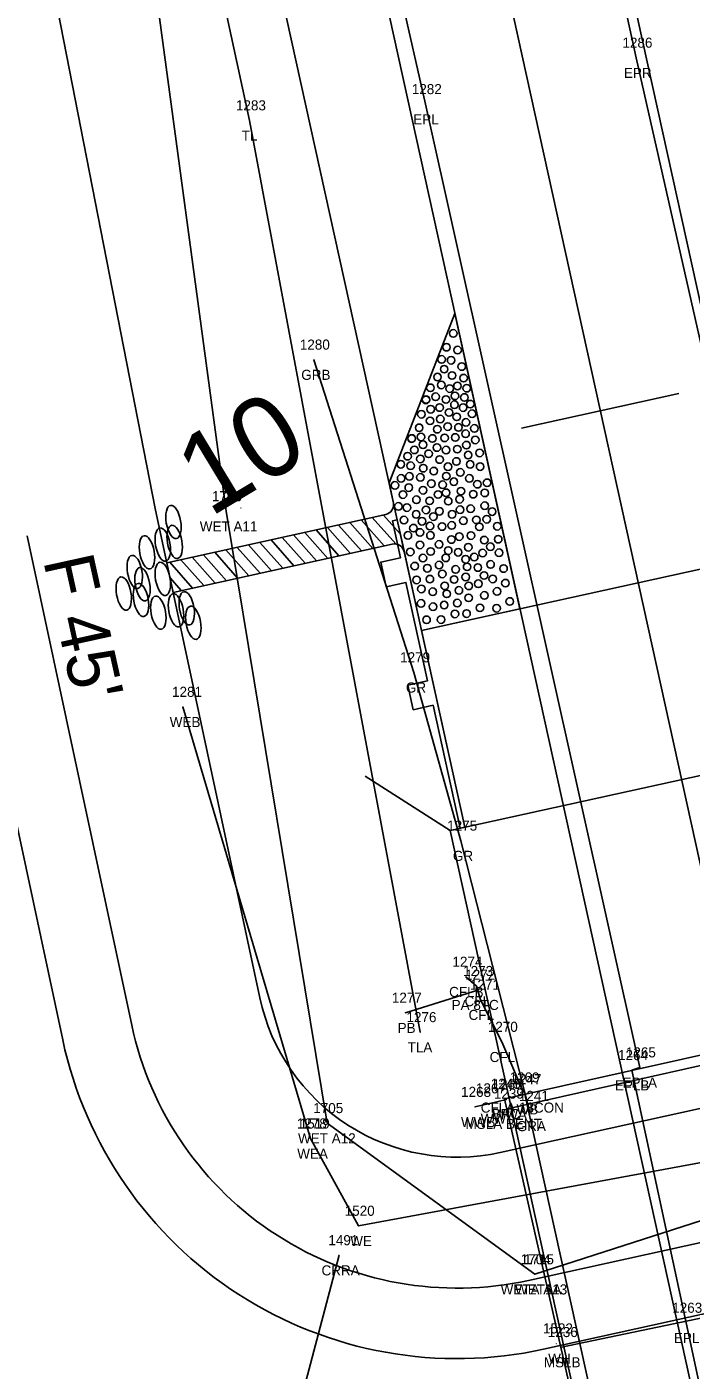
# Model space of a CAD drawing. Extents: x 2521558 to 2524785, y 882711 to 887632.
# Drawn here: x 2523710.8 to 2523776.7, y 885124.5 to 885257.9 of the extents above; entities that cross this region are included whole.
import ezdxf

# ---------------------------------------------------------------- set-up
doc = ezdxf.new("R2010")
doc.units = 0
for name, color, linetype in [('RD_EV_JW', 7, 'Continuous'), ('RD_EX_BldgApp', 7, 'Continuous'), ('RD_EX_BldgApp_txCode', 7, 'Continuous'), ('RD_EX_Bridge', 7, 'Continuous'), ('RD_EX_Bridge_txCode', 7, 'Continuous'), ('RD_EX_Conc', 7, 'Continuous'), ('RD_EX_Conc_txCode', 7, 'Continuous'), ('RD_EX_DR_Pipe', 7, 'Continuous'), ('RD_EX_DR_Pipe_txCode', 7, 'Continuous'), ('RD_EX_GuardRail', 7, 'Continuous'), ('RD_EX_GuardRail_txCode', 7, 'Continuous'), ('RD_EX_H2O', 7, 'Continuous'), ('RD_EX_H2O_txCode', 7, 'Continuous'), ('RD_EX_H2O_WetLd_txCode', 7, 'Continuous'), ('RD_EX_Misc', 7, 'Continuous'), ('RD_EX_Misc_txCode', 7, 'Continuous'), ('RD_EX_Road', 7, 'Continuous'), ('RD_EX_Road_txCode', 7, 'Continuous'), ('RD_EX_VEG', 7, 'Continuous'), ('RD_EX_VEG_txCode', 7, 'Continuous'), ('RD_HC_Cl', 7, 'Continuous'), ('RD_HC_Data_Tic', 7, 'Continuous'), ('RD_HC_TX_Sta50', 7, 'Continuous'), ('RD_PD_BCA', 7, 'Continuous'), ('RD_PD_Bridge', 7, 'Continuous'), ('RD_PD_CstnLmt', 7, 'Continuous'), ('RD_PD_DR_ErosCtrl', 7, 'Continuous'), ('RD_PD_Final_TrvlWay', 7, 'Continuous'), ('RD_PD_GR', 7, 'Continuous'), ('RD_PD_PaveShd', 7, 'Continuous'), ('RD_SMD_Locator', 7, 'Continuous')]:
    doc.layers.add(name, color=color, linetype=linetype)

# ---------------------------------------------------------------- blocks, each defined once
blk = doc.blocks.new('TBC1')
at = {"layer": 'RD_PD_GR'}
blk.add_lwpolyline([(12.5, 2.5), (15, 2.5), (15, 0.49), (25, 0.49), (25, 2.5), (27.5, 2.5), (27.5, 0.49), (31.25, 0.49), (31.25, 0), (0, 0), (0, 0.49), (12.5, 0.49)], close=True, dxfattribs=at)

msp = doc.modelspace()

# ---------------------------------------------------------------- linework, layer by layer
at = {"layer": 'RD_EV_JW'}
for points in [[(2523761.17, 885134.03), (2523740.58, 885149.03), (2523730.55, 885209.77), (2523710.6, 885357.47), (2523698.09, 885411.19), (2523674.93, 885498.62), (2523657.6, 885564.24), (2523640.82, 885610.87), (2523583.66, 885726.91), (2523539.21, 885693.17), (2523494.42, 885646.98)], [(2523761.17, 885134.03), (2523808.21, 885149.21), (2523821.91, 885178.64), (2523802.85, 885236.55), (2523777.81, 885305.56), (2523748.2, 885444.32), (2523730.68, 885516.88), (2523708.64, 885617.3), (2523698.71, 885662.02), (2523727.83, 885665.82), (2523757.3, 885671.75)]]:
    msp.add_lwpolyline(points, dxfattribs=at)
at = {"layer": 'RD_EX_BldgApp'}
msp.add_lwpolyline([(2523776.68, 885077.92), (2523768.27, 885115.31), (2523760.2, 885151.9)], dxfattribs=at)
at = {"layer": 'RD_EX_Bridge'}
for points in [[(2523774.91, 885077.6), (2523821.2, 885087.83), (2523805.06, 885161.89), (2523758.15, 885151.44), (2523774.91, 885077.6)], [(2523758.38, 885151.39), (2523756.7, 885150.99), (2523755.23, 885150.64)]]:
    msp.add_lwpolyline(points, dxfattribs=at)
at = {"layer": 'RD_EX_Conc'}
msp.add_lwpolyline([(2523760.04, 885152.08), (2523757.9, 885157.1), (2523755.8, 885161.28), (2523755.4, 885162.64), (2523754.34, 885163.56)], dxfattribs=at)
at = {"layer": 'RD_EX_DR_Pipe'}
msp.add_line((2523755.61, 885162.27), (2523748.33, 885159.99), dxfattribs=at)
at = {"layer": 'RD_EX_GuardRail'}
for p, q in [((2523749.16, 885193.78), (2523739.25, 885224.82)), ((2523753.83, 885177.07), (2523749.16, 885193.78)), ((2523760.65, 885150.24), (2523753.83, 885177.07))]:
    msp.add_line(p, q, dxfattribs=at)
at = {"layer": 'RD_EX_H2O'}
msp.add_line((2523738.91, 885147.5), (2523726.24, 885190.35), dxfattribs=at)
for points in [[(2523738.91, 885147.5), (2523743.69, 885138.84), (2523816.36, 885152.29), (2523822.43, 885163.3), (2523826.93, 885206.61)], [(2523741.75, 885135.92), (2523732.18, 885099.57), (2523664.9, 885060.26), (2523614.86, 885022.02), (2523558.95, 884972.63), (2523560.62, 884942.42), (2523490.01, 884911.76)]]:
    msp.add_lwpolyline(points, dxfattribs=at)
at = {"layer": 'RD_EX_Misc'}
for p, q in [((2523758.45, 885150.47), (2523805.66, 885161.06)), ((2523810.71, 885136.57), (2523763.83, 885126.8))]:
    msp.add_line(p, q, dxfattribs=at)
at = {"layer": 'RD_EX_Road'}
for p, q in [((2523771.24, 885254.79), (2523751.35, 885344.92)), ((2523750.32, 885250.18), (2523730.02, 885340.63)), ((2523792.78, 885159.31), (2523771.24, 885254.79)), ((2523771.58, 885154.56), (2523750.32, 885250.18)), ((2523770.8, 885154.29), (2523771.58, 885154.56)), ((2523776.18, 885129.21), (2523770.8, 885154.29)), ((2523781.52, 885104.77), (2523776.18, 885129.21))]:
    msp.add_line(p, q, dxfattribs=at)
at = {"layer": 'RD_EX_VEG'}
msp.add_lwpolyline([(2523749.81, 885158.06), (2523732.86, 885248.57), (2523691.62, 885438.95), (2523639.52, 885601.04)], dxfattribs=at)
at = {"layer": 'RD_HC_Cl'}
msp.add_line((2523641.17, 885794.2), (2524197.76, 883266.56), dxfattribs=at)
at = {"layer": 'RD_HC_Data_Tic'}
for q in [(2523775.47, 885221.48), (2523759.85, 885218.04)]:
    msp.add_line((2523767.66, 885219.76), q, dxfattribs=at)
at = {"layer": 'RD_PD_BCA'}
msp.add_line((2523703.95, 885205.86), (2523714.34, 885157.3), dxfattribs=at)
msp.add_lwpolyline([(2523762.05, 885126.6), (2523810.84, 885137.34)], dxfattribs=at)
msp.add_arc((2523753.45, 885165.66), 40, 192.0677, 282.4185, dxfattribs=at)
at = {"layer": 'RD_PD_Bridge'}
for p, q in [((2523749.94, 885197.94), (2523792.91, 885207.4)), ((2523754.24, 885178.41), (2523749.94, 885197.94)), ((2523752.77, 885178.09), (2523744.35, 885183.47))]:
    msp.add_line(p, q, dxfattribs=at)
for points in [[(2523798.67, 885188.19), (2523752.77, 885178.09)], [(2523752.77, 885178.09), (2523780.73, 885051.13)]]:
    msp.add_lwpolyline(points, dxfattribs=at)
at = {"layer": 'RD_PD_CstnLmt'}
for p, q in [((2523704.35, 885308.21), (2523723.51, 885210.04)), ((2523723.51, 885210.04), (2523733.89, 885161.48))]:
    msp.add_line(p, q, dxfattribs=at)
msp.add_lwpolyline([(2523757.75, 885146.13), (2523806.54, 885156.87)], dxfattribs=at)
msp.add_arc((2523753.45, 885165.66), 20, 192.0677, 282.4185, dxfattribs=at)
at = {"layer": 'RD_PD_DR_ErosCtrl'}
msp.add_line((2523710.8, 885207.32), (2523721.18, 885158.76), dxfattribs=at)
msp.add_lwpolyline([(2523760.55, 885133.43), (2523809.33, 885144.17)], dxfattribs=at)
msp.add_arc((2523753.45, 885165.66), 33, 192.0677, 282.4185, dxfattribs=at)
at = {"layer": 'RD_PD_Final_TrvlWay'}
for p, q in [((2523741.74, 885393.25), (2524015.93, 884148.08)), ((2523718.31, 885388.09), (2523992.49, 884142.92))]:
    msp.add_line(p, q, dxfattribs=at)
at = {"layer": 'RD_PD_GR'}
msp.add_line((2523747.52, 885208.93), (2523699.13, 885428.66), dxfattribs=at)
at = {"layer": 'RD_PD_PaveShd'}
for p, q in [((2523753.25, 885229.39), (2523746.71, 885212.59)), ((2523759.7, 885200.09), (2523753.25, 885229.39)), ((2523747.36, 885209.66), (2523746.71, 885212.59)), ((2523746.38, 885209.44), (2523724.66, 885204.65)), ((2523745.09, 885206.09), (2523742.82, 885208.66)), ((2523746.21, 885206.34), (2523743.94, 885208.91)), ((2523747.37, 885206.53), (2523745.05, 885209.15)), ((2523747.82, 885207.53), (2523746.17, 885209.4)), ((2523748, 885206.73), (2523747.36, 885209.66)), ((2523739.51, 885204.86), (2523737.23, 885207.43)), ((2523740.63, 885205.1), (2523738.35, 885207.67)), ((2523741.74, 885205.35), (2523739.47, 885207.92)), ((2523742.86, 885205.6), (2523740.59, 885208.17)), ((2523743.98, 885205.84), (2523741.7, 885208.41)), ((2523725.29, 885201.72), (2523747.02, 885206.51)), ((2523732.81, 885203.38), (2523730.53, 885205.95)), ((2523733.92, 885203.62), (2523731.65, 885206.19)), ((2523735.04, 885203.87), (2523732.77, 885206.44)), ((2523736.16, 885204.12), (2523733.88, 885206.69)), ((2523737.27, 885204.36), (2523735, 885206.93)), ((2523738.39, 885204.61), (2523736.12, 885207.18)), ((2523748, 885206.73), (2523749.94, 885197.94)), ((2523749.94, 885197.94), (2523748, 885206.73)), ((2523724.66, 885204.65), (2523725.29, 885201.72)), ((2523727.22, 885202.14), (2523724.95, 885204.71)), ((2523728.34, 885202.39), (2523726.06, 885204.96)), ((2523729.46, 885202.64), (2523727.18, 885205.21)), ((2523730.57, 885202.88), (2523728.3, 885205.45)), ((2523731.69, 885203.13), (2523729.42, 885205.7)), ((2523726.1, 885201.9), (2523724.98, 885203.17)), ((2523759.7, 885200.09), (2523749.94, 885197.94))]:
    msp.add_line(p, q, dxfattribs=at)
for centre in [(2523753.08, 885227.43), (2523753.08, 885227.43), (2523752.41, 885226.06), (2523752.41, 885226.06), (2523753.51, 885225.78), (2523753.51, 885225.78), (2523751.93, 885224.85), (2523751.93, 885224.85), (2523752.87, 885224.76), (2523752.87, 885224.76), (2523751.52, 885223.1), (2523752.18, 885223.88), (2523752.18, 885223.88), (2523752.97, 885223.25), (2523752.97, 885223.25), (2523753.92, 885224.14), (2523753.92, 885224.14), (2523754.11, 885222.99), (2523754.11, 885222.99), (2523750.81, 885222.03), (2523750.81, 885222.03), (2523751.89, 885222.31), (2523751.89, 885222.31), (2523752.73, 885221.95), (2523752.73, 885221.95), (2523753.5, 885222.22), (2523753.5, 885222.22), (2523754.42, 885221.99), (2523754.42, 885221.99), (2523750.37, 885220.83), (2523750.38, 885220.87), (2523751.33, 885221.14), (2523751.33, 885221.14), (2523752.36, 885220.87), (2523752.36, 885220.87), (2523753.2, 885220.35), (2523753.2, 885220.35), (2523753.25, 885221.23), (2523753.25, 885221.23), (2523754.19, 885221.07), (2523754.19, 885221.07), (2523754.77, 885220.41), (2523754.77, 885220.41), (2523749.92, 885219.4), (2523749.92, 885219.4), (2523750.84, 885219.9), (2523750.84, 885219.9), (2523751.73, 885220.07), (2523751.73, 885220.07), (2523751.79, 885218.93), (2523751.79, 885218.93), (2523752.67, 885219.58), (2523752.67, 885219.58), (2523753.43, 885219.15), (2523753.43, 885219.15), (2523754.06, 885220.06), (2523754.06, 885220.06), (2523754.95, 885219.46), (2523754.95, 885219.46), (2523749.7, 885218.06), (2523749.7, 885218.06), (2523750.78, 885218.75), (2523750.78, 885218.75), (2523751.5, 885217.92), (2523751.5, 885217.92), (2523752.53, 885218.18), (2523752.53, 885218.18), (2523753.6, 885218.1), (2523753.6, 885218.1), (2523754.34, 885218.6), (2523754.34, 885218.6), (2523755.18, 885218), (2523755.18, 885218), (2523748.95, 885216.99), (2523748.96, 885217), (2523749.87, 885217.15), (2523749.87, 885217.15), (2523750.08, 885216.38), (2523750.08, 885216.38), (2523751.01, 885217), (2523751.01, 885217), (2523752.22, 885217.06), (2523752.22, 885217.06), (2523753.28, 885217.1), (2523753.28, 885217.1), (2523754.3, 885217.47), (2523754.3, 885217.47), (2523754.38, 885216.34), (2523754.38, 885216.34), (2523755.27, 885216.85), (2523755.27, 885216.85), (2523748.55, 885215.24), (2523748.55, 885215.24), (2523749.23, 885215.87), (2523749.23, 885215.87), (2523749.82, 885214.97), (2523749.82, 885214.97), (2523750.64, 885215.48), (2523750.64, 885215.48), (2523751.46, 885216.1), (2523751.46, 885216.1), (2523751.73, 885214.91), (2523751.73, 885214.91), (2523752.37, 885215.85), (2523752.37, 885215.85), (2523753.48, 885215.94), (2523753.48, 885215.94), (2523754.56, 885215.35), (2523754.56, 885215.35), (2523755.7, 885215.56), (2523755.7, 885215.56), (2523747.88, 885214.44), (2523747.88, 885214.44), (2523748.85, 885214.3), (2523748.85, 885214.3), (2523750.1, 885214.05), (2523750.1, 885214.05), (2523751.15, 885213.76), (2523751.15, 885213.76), (2523752.56, 885214.2), (2523752.56, 885214.2), (2523753.4, 885214.72), (2523753.4, 885214.72), (2523753.78, 885213.63), (2523753.78, 885213.63), (2523754.76, 885214.43), (2523754.76, 885214.43), (2523755.75, 885214.21), (2523755.75, 885214.21), (2523747.3, 885212.34), (2523747.3, 885212.34), (2523747.3, 885212.34), (2523747.91, 885213.04), (2523747.91, 885213.04), (2523748.73, 885213.24), (2523748.73, 885213.24), (2523749.82, 885213.14), (2523749.82, 885213.14), (2523750.91, 885212.52), (2523750.91, 885212.52), (2523752.03, 885212.41), (2523752.03, 885212.41), (2523752.39, 885213.26), (2523752.39, 885213.26), (2523753.14, 885212.71), (2523753.14, 885212.71), (2523754.68, 885213.04), (2523754.68, 885213.04), (2523755.48, 885212.46), (2523755.48, 885212.46), (2523756.44, 885212.6), (2523756.44, 885212.6), (2523748.09, 885211.43), (2523748.09, 885211.43), (2523748.67, 885212.12), (2523748.67, 885212.12), (2523749.43, 885210.92), (2523749.43, 885210.92), (2523750.09, 885211.86), (2523750.09, 885211.86), (2523751.57, 885211.44), (2523751.57, 885211.44), (2523752.37, 885211.61), (2523752.37, 885211.61), (2523753.71, 885210.96), (2523753.71, 885210.96), (2523753.84, 885211.77), (2523753.84, 885211.77), (2523755.06, 885211.47), (2523755.06, 885211.47), (2523756.21, 885211.6), (2523756.21, 885211.6), (2523747.64, 885210.26), (2523747.64, 885210.26), (2523748.49, 885210.14), (2523748.49, 885210.14), (2523750.38, 885209.91), (2523750.38, 885209.91), (2523750.73, 885210.81), (2523750.73, 885210.81), (2523751.7, 885209.77), (2523751.7, 885209.77), (2523752.58, 885210.78), (2523752.58, 885210.78), (2523753.76, 885209.93), (2523753.76, 885209.93), (2523754.8, 885210.03), (2523754.8, 885210.03), (2523756.2, 885210.33), (2523756.2, 885210.33), (2523756.94, 885209.74), (2523748.19, 885208.9), (2523748.19, 885208.9), (2523749.4, 885209.47), (2523749.4, 885209.47), (2523749.98, 885208.78), (2523749.98, 885208.78), (2523750.77, 885208.31), (2523750.77, 885208.31), (2523751.11, 885209.24), (2523751.11, 885209.24), (2523751.97, 885208.26), (2523751.97, 885208.26), (2523752.93, 885208.37), (2523752.93, 885208.37), (2523752.97, 885209.47), (2523752.97, 885209.47), (2523754.09, 885208.84), (2523754.09, 885208.84), (2523755.38, 885208.92), (2523755.38, 885208.92), (2523755.68, 885208.23), (2523755.68, 885208.23), (2523756.4, 885208.98), (2523756.4, 885208.98), (2523757.45, 885208.29), (2523757.45, 885208.29), (2523748.58, 885207.38), (2523748.58, 885207.38), (2523749.13, 885208.1), (2523749.13, 885208.1), (2523749.78, 885207.67), (2523749.78, 885207.67), (2523750.82, 885207.38), (2523750.82, 885207.38), (2523752.9, 885206.97), (2523752.9, 885206.97), (2523753.68, 885207.26), (2523753.68, 885207.26), (2523754.84, 885207.36), (2523754.84, 885207.36), (2523756.16, 885206.91), (2523756.16, 885206.91), (2523757.54, 885207), (2523757.54, 885207), (2523748.82, 885205.74), (2523748.82, 885205.74), (2523749.78, 885206.43), (2523749.78, 885206.43), (2523750.84, 885205.78), (2523750.84, 885205.78), (2523751.67, 885206.49), (2523751.67, 885206.49), (2523752.58, 885205.87), (2523752.58, 885205.87), (2523753.57, 885205.7), (2523753.57, 885205.7), (2523754.57, 885206.2), (2523754.57, 885206.2), (2523755.99, 885205.63), (2523755.99, 885205.63), (2523756.77, 885206.26), (2523756.77, 885206.26), (2523757.63, 885205.66), (2523757.63, 885205.66), (2523749.26, 885204.33), (2523749.26, 885204.33), (2523750.07, 885205.13), (2523750.07, 885205.13), (2523751.68, 885204.44), (2523751.68, 885204.44), (2523752.34, 885205.15), (2523752.34, 885205.15), (2523754.3, 885205.01), (2523754.3, 885205.01), (2523754.46, 885204.26), (2523755.16, 885205.23), (2523755.16, 885205.23), (2523755.52, 885204.19), (2523755.52, 885204.19), (2523756.78, 885204.5), (2523756.78, 885204.5), (2523749.44, 885202.96), (2523749.44, 885202.96), (2523750.51, 885204.12), (2523750.51, 885204.12), (2523750.76, 885203.04), (2523750.76, 885203.04), (2523751.99, 885203.55), (2523751.99, 885203.55), (2523753.17, 885203), (2523753.17, 885203), (2523753.31, 885204), (2523753.31, 885204), (2523754.32, 885203.25), (2523754.32, 885203.25), (2523756.14, 885203.4), (2523756.14, 885203.4), (2523757, 885203.06), (2523757, 885203.06), (2523758.07, 885204.09), (2523758.07, 885204.09), (2523749.92, 885202.06), (2523749.92, 885202.06), (2523751.05, 885201.79), (2523751.05, 885201.79), (2523752.24, 885202.37), (2523752.24, 885202.37), (2523752.44, 885201.58), (2523752.44, 885201.58), (2523753.64, 885201.92), (2523753.64, 885201.92), (2523754.62, 885202.37), (2523754.62, 885202.37), (2523755.57, 885202.58), (2523755.57, 885202.58), (2523757.43, 885201.82), (2523757.43, 885201.82), (2523758.26, 885202.64), (2523758.26, 885202.64), (2523749.89, 885200.63), (2523749.89, 885200.63), (2523751.08, 885200.3), (2523751.08, 885200.3), (2523752.18, 885200.46), (2523752.18, 885200.46), (2523753.48, 885200.66), (2523753.48, 885200.66), (2523754.61, 885201.18), (2523754.61, 885201.18), (2523755.73, 885200.19), (2523755.73, 885200.19), (2523756.17, 885201.42), (2523756.17, 885201.42), (2523758.69, 885200.82), (2523758.69, 885200.82), (2523750.43, 885199), (2523750.43, 885199), (2523750.43, 885199), (2523751.87, 885199.02), (2523751.87, 885199.02), (2523753.25, 885199.58), (2523753.25, 885199.58), (2523754.4, 885199.62), (2523754.4, 885199.62), (2523757.38, 885200.14), (2523757.38, 885200.14)]:
    msp.add_circle(centre, 0.375, dxfattribs=at)
for centre, start, end in [((2523746.16, 885210.42), 282.4481, 12.4185), ((2523747.24, 885205.54), 12.4185, 102.4481)]:
    msp.add_arc(centre, 1, start, end, dxfattribs=at)
for centre in [(2523725.32, 885208.71), (2523722.69, 885205.7), (2523722.69, 885205.7), (2523724.26, 885206.47), (2523724.26, 885206.47), (2523725.44, 885206.73), (2523721.48, 885203.75), (2523721.48, 885203.75), (2523724.26, 885203.06), (2523724.26, 885203.06), (2523720.39, 885201.6), (2523720.39, 885201.6), (2523722.25, 885202.53), (2523722.25, 885202.53), (2523722.1, 885200.97), (2523722.1, 885200.97), (2523723.82, 885199.71), (2523723.82, 885199.71), (2523725.57, 885199.94), (2523725.57, 885199.94), (2523726.64, 885200.14), (2523726.64, 885200.14), (2523727.29, 885198.71), (2523727.29, 885198.71)]:
    msp.add_ellipse(centre, major_axis=(-0.29, 1.65), ratio=0.429445, dxfattribs=at)
at = {"layer": 'RD_SMD_Locator'}
for centre in [(2523771.24, 885254.79), (2523750.32, 885250.18), (2523732.86, 885248.57), (2523739.25, 885224.82), (2523732.01, 885210.1), (2523749.16, 885193.78), (2523726.24, 885190.35), (2523753.83, 885177.07), (2523754.34, 885163.56), (2523755.4, 885162.64), (2523755.61, 885162.27), (2523755.8, 885161.28), (2523748.33, 885159.99), (2523749.81, 885158.06), (2523757.9, 885157.1), (2523770.8, 885154.29), (2523771.58, 885154.56), (2523758.15, 885151.44), (2523758.38, 885151.39), (2523760.04, 885152.08), (2523760.2, 885151.9), (2523755.23, 885150.64), (2523756.7, 885150.99), (2523758.45, 885150.47), (2523760.65, 885150.24), (2523740.58, 885149.03), (2523738.91, 885147.5), (2523738.91, 885147.5), (2523743.69, 885138.84), (2523741.75, 885135.92), (2523761.17, 885134.03), (2523761.17, 885134.03), (2523776.18, 885129.21), (2523763.32, 885127.16), (2523763.83, 885126.8)]:
    msp.add_circle(centre, 0.001, dxfattribs=at)

# ---------------------------------------------------------------- block references
at = {"layer": 'RD_PD_Bridge', "rotation": 102.41848259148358}
msp.add_blockref('TBC1', (2523754.24, 885178.41), dxfattribs=at)

# ---------------------------------------------------------------- texts
at = {"layer": 'RD_EX_BldgApp_txCode'}
for s, p in [('1247', (2523758.86, 885152.9)), ('WB', (2523759.36, 885149.9)), ('1522', (2523761.98, 885128.16)), ('WH', (2523762.5, 885125.16))]:
    msp.add_text(s, height=1, dxfattribs=at).set_placement(p)
at = {"layer": 'RD_EX_Bridge_txCode'}
for s, p in [('1268', (2523753.86, 885151.64)), ('1267', (2523755.33, 885151.99)), ('1245', (2523756.8, 885152.44)), ('1266', (2523756.98, 885152.39)), ('WW', (2523755.8, 885148.99)), ('WWA', (2523756.98, 885149.39)), ('BRC', (2523756.89, 885149.44)), ('WWB', (2523753.85, 885148.64))]:
    msp.add_text(s, height=1, dxfattribs=at).set_placement(p)
at = {"layer": 'RD_EX_Conc_txCode'}
for s, p in [('1274', (2523753, 885164.56)), ('1273', (2523754.06, 885163.64)), ('1271', (2523754.74, 885162.28)), ('CFLB', (2523752.67, 885161.56)), ('CFL', (2523754.2, 885160.64)), ('CFL', (2523754.6, 885159.28)), ('1270', (2523756.51, 885158.1)), ('CFL', (2523756.69, 885155.1)), ('1269', (2523758.67, 885153.08)), ('CFLA 18CON', (2523755.81, 885150.08))]:
    msp.add_text(s, height=1, dxfattribs=at).set_placement(p)
at = {"layer": 'RD_EX_DR_Pipe_txCode'}
for s, p in [('1272', (2523754.27, 885163.27)), ('1277', (2523746.99, 885160.99)), ('PA 8TC', (2523752.92, 885160.27)), ('PB', (2523747.56, 885157.99))]:
    msp.add_text(s, height=1, dxfattribs=at).set_placement(p)
at = {"layer": 'RD_EX_GuardRail_txCode'}
for s, p in [('1280', (2523737.86, 885225.82)), ('GRB', (2523738, 885222.82)), ('1279', (2523747.81, 885194.78)), ('GR', (2523748.38, 885191.78)), ('1275', (2523752.48, 885178.07)), ('GR', (2523753.05, 885175.07)), ('1241', (2523759.59, 885151.24)), ('GRA', (2523759.38, 885148.24))]:
    msp.add_text(s, height=1, dxfattribs=at).set_placement(p)
at = {"layer": 'RD_EX_H2O_txCode'}
for s, p in [('1281', (2523725.18, 885191.35)), ('WEB', (2523724.95, 885188.35)), ('1278', (2523737.56, 885148.5)), ('1519', (2523737.85, 885148.5)), ('WEA', (2523737.6, 885145.5)), ('WEA', (2523737.6, 885145.5)), ('1520', (2523742.31, 885139.84)), ('1491', (2523740.69, 885136.92)), ('WE', (2523742.86, 885136.84)), ('CRRA', (2523740.01, 885133.92))]:
    msp.add_text(s, height=1, dxfattribs=at).set_placement(p)
at = {"layer": 'RD_EX_H2O_WetLd_txCode'}
for s, p in [('1706', (2523729.14, 885210.77)), ('WET A11', (2523727.93, 885207.77)), ('1705', (2523739.19, 885150.03)), ('WET A12', (2523737.68, 885147.03)), ('1704', (2523759.78, 885135.03)), ('1715', (2523760.1, 885135.03)), ('WETA A13', (2523757.78, 885132.03)), ('WET1A', (2523759.21, 885132.03))]:
    msp.add_text(s, height=1, dxfattribs=at).set_placement(p)
at = {"layer": 'RD_EX_Misc_txCode'}
for s, p in [('1239', (2523757.11, 885151.47)), ('MSLA BENT', (2523754.3, 885148.47)), ('1236', (2523762.46, 885127.8)), ('MSLB', (2523762.07, 885124.8))]:
    msp.add_text(s, height=1, dxfattribs=at).set_placement(p)
at = {"layer": 'RD_EX_Road_txCode'}
for s, p in [('1286', (2523769.87, 885255.79)), ('EPR', (2523770.01, 885252.79)), ('1282', (2523748.97, 885251.18)), ('EPL', (2523749.11, 885248.18)), ('1265', (2523770.21, 885155.56)), ('1264', (2523769.43, 885155.29)), ('EPLB', (2523769.12, 885152.29)), ('EPLA', (2523769.88, 885152.56)), ('1263', (2523774.81, 885130.21)), ('EPL', (2523774.97, 885127.21))]:
    msp.add_text(s, height=1, dxfattribs=at).set_placement(p)
at = {"layer": 'RD_EX_VEG_txCode'}
for s, p in [('1283', (2523731.52, 885249.57)), ('TL', (2523732.09, 885246.57)), ('1276', (2523748.44, 885159.06)), ('TLA', (2523748.55, 885156.06))]:
    msp.add_text(s, height=1, dxfattribs=at).set_placement(p)
at = {"layer": 'RD_HC_TX_Sta50'}
msp.add_text('10', height=8, rotation=31.1184, dxfattribs=at).set_placement((2523728.92, 885209.12))
at = {"layer": 'RD_PD_CstnLmt'}
msp.add_text("F 45'", height=5, rotation=282.4185, dxfattribs=at).set_placement((2523712.38, 885204.89))

doc.saveas('drawing.dxf')
